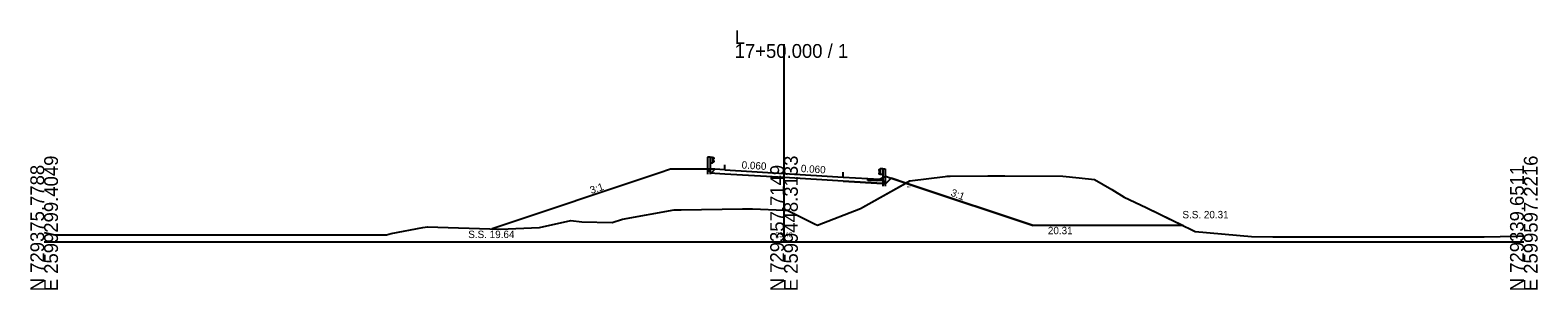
# Model space of a CAD drawing. Extents: x -26 to 3303, y -10 to 9555.
# Drawn here: x 997.2 to 1302.8, y 4990.3 to 5042.9 of the extents above; entities that cross this region are included whole.
import ezdxf

# ---------------------------------------------------------------- set-up
doc = ezdxf.new("R2010")
doc.units = 0
for name, color, linetype in [('Exist Cross Section Cell', 7, 'Continuous'), ('Exist XS Center Line Elevation Label', 7, 'Continuous'), ('Exist XS Ground Line', 7, 'Continuous'), ('Prop XS Ditch Slope Text', 7, 'Continuous'), ('Prop XS Ditch Standard Text', 7, 'Continuous'), ('Prop XS Dump Level', 7, 'Continuous'), ('Prop XS Earthwork Shape', 7, 'Continuous'), ('Prop XS EOT Tick Mark', 7, 'Continuous'), ('Prop XS Finish Grade', 7, 'Continuous'), ('Prop XS Finish Grade Earthwork', 7, 'Continuous'), ('Prop XS Finish Grade Paved Shoulder', 7, 'Continuous'), ('Prop XS Finish Grade Pavement', 7, 'Continuous'), ('Prop XS Pvmt Edge Slope', 7, 'Continuous'), ('Prop XS SE Text', 7, 'Continuous'), ('Prop XS Side Slope Text', 7, 'Continuous'), ('Prop XS SS Elevation Text', 7, 'Continuous'), ('Prop XS Subgrade Earthwork', 7, 'Continuous'), ('Typical Curb CELL', 7, 'Continuous'), ('Typical Guardrail CELL', 7, 'Continuous')]:
    doc.layers.add(name, color=color, linetype=linetype)

msp = doc.modelspace()

# ---------------------------------------------------------------- linework, layer by layer
at = {"layer": 'Exist Cross Section Cell'}
for p, q in [((1150, 5000), (1150, 5040.07)), ((1000, 5000), (1150, 5000)), ((1150, 5000), (1300, 5000))]:
    msp.add_line(p, q, dxfattribs=at)
at = {"layer": 'Exist XS Ground Line'}
msp.add_lwpolyline([(1000, 5001.9), (1002.19, 5001.47), (1041.98, 5001.47), (1069.4, 5001.47), (1070.35, 5001.7), (1076.75, 5002.89), (1077.73, 5003.07), (1092.46, 5002.59), (1100.41, 5002.91), (1106.77, 5004.35), (1109.01, 5004.08), (1115.19, 5003.95), (1117.25, 5004.61), (1127.7, 5006.5), (1129.12, 5006.53), (1141.56, 5006.71), (1142.15, 5006.73), (1143.63, 5006.67), (1150, 5006.46), (1150.63, 5006.44), (1156.21, 5003.65), (1156.77, 5003.41), (1165.54, 5006.75), (1175.52, 5012.37), (1182.69, 5013.28), (1183.05, 5013.34), (1183.68, 5013.34), (1191.33, 5013.35), (1194.74, 5013.36), (1206.52, 5013.3), (1209.86, 5012.98), (1212.98, 5012.63), (1216.45, 5010.59), (1218.97, 5009.05), (1223.41, 5006.98), (1233.38, 5002.1), (1244.76, 5001.1), (1249.1, 5001), (1261.25, 5001), (1264, 5001), (1273.2, 5001), (1287.04, 5001), (1290.71, 5001), (1291.94, 5001), (1298.44, 5001.18), (1300, 5001.23)], dxfattribs=at)
at = {"layer": 'Prop XS Dump Level'}
for p, q in [((1138, 5014.58), (1150, 5013.86)), ((1138, 5014.58), (1150, 5013.86)), ((1150, 5013.86), (1162, 5013.14)), ((1150, 5013.86), (1162, 5013.14))]:
    msp.add_line(p, q, dxfattribs=at)
at = {"layer": 'Prop XS Earthwork Shape'}
for points in [[(1143.63, 5006.67), (1150, 5006.46), (1150.63, 5006.44), (1156.21, 5003.65), (1156.77, 5003.41), (1165.54, 5006.75), (1174.72, 5011.92), (1171.7, 5012.92), (1170.56, 5011.79), (1170, 5011.82), (1162, 5012.3), (1150, 5013.02), (1138, 5013.74), (1136, 5013.86), (1135.21, 5013.91), (1134.43, 5014.7), (1127, 5014.7), (1124.64, 5013.91), (1090.84, 5002.64), (1092.46, 5002.59), (1100.41, 5002.91), (1106.77, 5004.35), (1109.01, 5004.08), (1115.19, 5003.95), (1117.25, 5004.61), (1127.7, 5006.5), (1129.12, 5006.53), (1141.56, 5006.71), (1142.15, 5006.73)], [(1136, 5013.86), (1135.21, 5013.91), (1134.43, 5014.7), (1127, 5014.7), (1124.64, 5013.91), (1090.84, 5002.64), (1092.46, 5002.59), (1100.41, 5002.91), (1106.77, 5004.35), (1109.01, 5004.08), (1115.19, 5003.95), (1117.25, 5004.61), (1127.7, 5006.5), (1129.12, 5006.53), (1141.56, 5006.71), (1142.15, 5006.73), (1143.63, 5006.67), (1150, 5006.46), (1150.63, 5006.44), (1156.21, 5003.65), (1156.77, 5003.41), (1165.54, 5006.75), (1174.72, 5011.92), (1171.7, 5012.92), (1170.56, 5011.79), (1170, 5011.82), (1162, 5012.3), (1150, 5013.02), (1138, 5013.74)], [(1209.86, 5012.98), (1212.98, 5012.63), (1216.45, 5010.59), (1218.97, 5009.05), (1223.41, 5006.98), (1230.91, 5003.31), (1200.53, 5003.31), (1176.5, 5011.32), (1174.72, 5011.92), (1175.52, 5012.37), (1182.69, 5013.28), (1183.05, 5013.34), (1183.68, 5013.34), (1191.33, 5013.35), (1194.74, 5013.36), (1206.52, 5013.3)], [(1218.97, 5009.05), (1223.41, 5006.98), (1230.91, 5003.31), (1200.53, 5003.31), (1176.5, 5011.32), (1174.72, 5011.92), (1175.52, 5012.37), (1182.69, 5013.28), (1183.05, 5013.34), (1183.68, 5013.34), (1191.33, 5013.35), (1194.74, 5013.36), (1206.52, 5013.3), (1209.86, 5012.98), (1212.98, 5012.63), (1216.45, 5010.59)]]:
    msp.add_lwpolyline(points, close=True, dxfattribs=at)
at = {"layer": 'Prop XS EOT Tick Mark'}
for p, q in [((1138, 5014.58), (1138, 5015.58)), ((1162, 5013.14), (1162, 5014.14))]:
    msp.add_line(p, q, dxfattribs=at)
at = {"layer": 'Prop XS Finish Grade'}
for p, q in [((1136, 5014.7), (1134.43, 5014.7)), ((1170.03, 5013.02), (1170.6, 5013.29)), ((1170.6, 5013.29), (1171.7, 5012.92))]:
    msp.add_line(p, q, dxfattribs=at)
at = {"layer": 'Prop XS Finish Grade Earthwork'}
for p, q in [((1124.64, 5013.91), (1090.84, 5002.64)), ((1127, 5014.7), (1124.64, 5013.91)), ((1134.43, 5014.7), (1127, 5014.7)), ((1171.7, 5012.92), (1176.5, 5011.32)), ((1176.5, 5011.32), (1200.53, 5003.31)), ((1230.91, 5003.31), (1200.53, 5003.31))]:
    msp.add_line(p, q, dxfattribs=at)
at = {"layer": 'Prop XS Finish Grade Paved Shoulder'}
for p, q in [((1138, 5014.58), (1136, 5014.7)), ((1162, 5013.14), (1167, 5012.84))]:
    msp.add_line(p, q, dxfattribs=at)
at = {"layer": 'Prop XS Finish Grade Pavement'}
for p, q in [((1138, 5014.58), (1150, 5013.86)), ((1150, 5013.86), (1162, 5013.14))]:
    msp.add_line(p, q, dxfattribs=at)
at = {"layer": 'Prop XS Pvmt Edge Slope'}
for p, q in [((1135.21, 5013.91), (1134.43, 5014.7)), ((1136, 5014.7), (1135.21, 5013.91)), ((1170.01, 5012.34), (1170.56, 5011.79)), ((1170.56, 5011.79), (1171.7, 5012.92))]:
    msp.add_line(p, q, dxfattribs=at)
at = {"layer": 'Prop XS Subgrade Earthwork'}
for p, q in [((1135.21, 5013.91), (1134.43, 5014.7)), ((1136, 5013.86), (1135.21, 5013.91)), ((1138, 5013.74), (1136, 5013.86)), ((1150, 5013.02), (1138, 5013.74)), ((1162, 5012.3), (1150, 5013.02)), ((1162, 5012.3), (1170, 5011.82)), ((1170, 5011.82), (1170.56, 5011.79)), ((1170.56, 5011.79), (1171.7, 5012.92))]:
    msp.add_line(p, q, dxfattribs=at)
at = {"layer": 'Typical Curb CELL'}
for p, q in [((1166.99, 5012.42), (1167, 5012.82)), ((1170.01, 5012.34), (1166.99, 5012.42)), ((1167, 5012.84), (1167, 5012.84)), ((1167.01, 5012.83), (1169.33, 5012.69)), ((1167.23, 5012.56), (1167.32, 5012.68)), ((1167.35, 5012.57), (1167.23, 5012.56)), ((1167.32, 5012.68), (1167.35, 5012.57)), ((1167.99, 5012.49), (1168.06, 5012.61)), ((1168.16, 5012.53), (1167.99, 5012.49)), ((1168.06, 5012.61), (1168.16, 5012.53)), ((1168.48, 5012.53), (1168.57, 5012.65)), ((1168.6, 5012.54), (1168.48, 5012.53)), ((1168.57, 5012.65), (1168.6, 5012.54)), ((1169.24, 5012.46), (1169.31, 5012.58)), ((1169.41, 5012.5), (1169.24, 5012.46)), ((1169.31, 5012.58), (1169.41, 5012.5)), ((1169.33, 5012.69), (1170.03, 5013.02)), ((1169.83, 5012.69), (1169.84, 5012.6)), ((1169.98, 5012.64), (1169.83, 5012.69)), ((1169.84, 5012.6), (1169.98, 5012.64)), ((1170.01, 5012.34), (1170.03, 5013.02))]:
    msp.add_line(p, q, dxfattribs=at)
for centre in [(1167.09, 5012.66), (1167.13, 5012.78), (1167.49, 5012.7), (1167.55, 5012.52), (1167.6, 5012.48), (1167.64, 5012.61), (1167.71, 5012.6), (1167.76, 5012.63), (1167.81, 5012.52), (1168, 5012.55), (1168.21, 5012.53), (1168.23, 5012.58), (1168.24, 5012.64), (1168.29, 5012.49), (1168.39, 5012.54), (1168.48, 5012.54), (1168.6, 5012.49), (1168.8, 5012.48), (1168.85, 5012.45), (1168.89, 5012.58), (1169.01, 5012.6), (1169.06, 5012.48), (1169.25, 5012.52), (1169.28, 5012.42), (1169.46, 5012.5), (1169.48, 5012.55), (1169.73, 5012.51), (1169.85, 5012.46), (1169.95, 5012.73)]:
    msp.add_circle(centre, 0.00802, dxfattribs=at)
msp.add_arc((1167.01, 5012.82), 0.0104, 86.5213, 178.5693, dxfattribs=at)
at = {"layer": 'Typical Guardrail CELL'}
for p, q in [((1135, 5017.18), (1134.5, 5017.18)), ((1134.5, 5017.18), (1134.5, 5014.7)), ((1135, 5017.18), (1135, 5014.7)), ((1135, 5017.18), (1135.5, 5017.18)), ((1135.5, 5017.18), (1135.5, 5016.02)), ((1135.5, 5017.18), (1135.79, 5016.98)), ((1135.5, 5016.65), (1135.79, 5016.85)), ((1135.5, 5016.6), (1135.5, 5016.65)), ((1135.5, 5016.6), (1135.5, 5016.55)), ((1135.5, 5016.55), (1135.79, 5016.35)), ((1135, 5014.7), (1134.5, 5014.7)), ((1134.5, 5014.7), (1134.5, 5013.69)), ((1135, 5016.02), (1135.5, 5016.02)), ((1135, 5014.7), (1135, 5013.69)), ((1135.5, 5016.02), (1135.79, 5016.22)), ((1169.53, 5014.8), (1169.24, 5014.6)), ((1169.53, 5014.27), (1169.24, 5014.47)), ((1169.53, 5014.18), (1169.24, 5013.97)), ((1169.53, 5013.64), (1169.24, 5013.84)), ((1170.03, 5014.8), (1169.53, 5014.8)), ((1169.53, 5014.8), (1169.53, 5013.64)), ((1169.53, 5014.22), (1169.53, 5014.27)), ((1169.53, 5014.22), (1169.53, 5014.18)), ((1170.03, 5013.64), (1169.53, 5013.64)), ((1170.03, 5014.8), (1170.03, 5012.32)), ((1170.03, 5014.8), (1170.53, 5014.8)), ((1170.53, 5014.8), (1170.53, 5012.32)), ((1170.03, 5012.32), (1170.53, 5012.32)), ((1170.03, 5012.32), (1170.03, 5011.31)), ((1170.53, 5012.32), (1170.53, 5011.31))]:
    msp.add_line(p, q, dxfattribs=at)
for centre, start, end in [((1135.74, 5016.91), 304.9888, 54.997), ((1135.74, 5016.29), 304.9634, 54.9941), ((1169.29, 5014.54), 125.003, 235.0112), ((1169.29, 5013.91), 125.0059, 235.0366)]:
    msp.add_arc(centre, 0.0776, start, end, dxfattribs=at)

# ---------------------------------------------------------------- texts
at = {"layer": 'Exist Cross Section Cell'}
for s, p in [('L', (1140, 5040.07)), ('17+50.000 / 1', (1140, 5037.27))]:
    msp.add_text(s, height=2.8, dxfattribs=at).set_placement(p)
for s, p in [('E 2599299.4049', (1002.8, 4990)), ('E 2599448.3133', (1152.8, 4990)), ('E 2599597.2216', (1302.8, 4990)), ('N 729375.7788', (1000, 4990)), ('N 729357.7149', (1150, 4990)), ('N 729339.6511', (1300, 4990))]:
    msp.add_text(s, height=2.8, rotation=90, dxfattribs=at).set_placement(p)
at = {"layer": 'Exist XS Center Line Elevation Label'}
msp.add_text('23.46', height=1, dxfattribs=at).set_placement((1148.26, 5000.96))
at = {"layer": 'Prop XS Ditch Slope Text'}
msp.add_text('3:1', height=1.5, rotation=338.8386, dxfattribs=at).set_placement((1183.68, 5009.4))
at = {"layer": 'Prop XS Ditch Standard Text'}
msp.add_text('20.31', height=1.5, dxfattribs=at).set_placement((1203.5, 5001.56))
at = {"layer": 'Prop XS Dump Level'}
for s, height, p in [('Case1', 0.04, (1130, 5014.66)), ('Case1', 0.04, (1170, 5012.5)), ('Case1', 0.04, (1173, 5012.38)), ('Eop', 0.3, (1175, 5011.01))]:
    msp.add_text(s, height=height, dxfattribs=at).set_placement(p)
at = {"layer": 'Prop XS SE Text'}
for p in [(1141.38, 5014.87), (1141.38, 5014.87), (1153.38, 5014.15), (1153.38, 5014.15)]:
    msp.add_text('0.060', height=1.5, rotation=356.5664, dxfattribs=at).set_placement(p)
at = {"layer": 'Prop XS Side Slope Text'}
msp.add_text('3:1', height=1.5, rotation=18.4349, dxfattribs=at).set_placement((1110.95, 5009.7))
at = {"layer": 'Prop XS SS Elevation Text'}
for s, p in [('S.S. 20.31', (1230.78, 5004.78)), ('S.S. 19.64', (1085.98, 5000.78))]:
    msp.add_text(s, height=1.5, dxfattribs=at).set_placement(p)

doc.saveas('drawing.dxf')
